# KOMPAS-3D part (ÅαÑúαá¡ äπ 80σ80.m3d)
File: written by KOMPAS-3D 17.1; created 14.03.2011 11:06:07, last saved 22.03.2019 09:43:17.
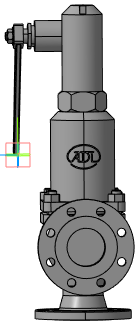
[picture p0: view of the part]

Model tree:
1. Плоскость XY
2. Плоскость ZX
3. Плоскость ZY
4. Ось X
5. Ось Y
6. Ось Z
7. Начало координат
8. Операция без истории:2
